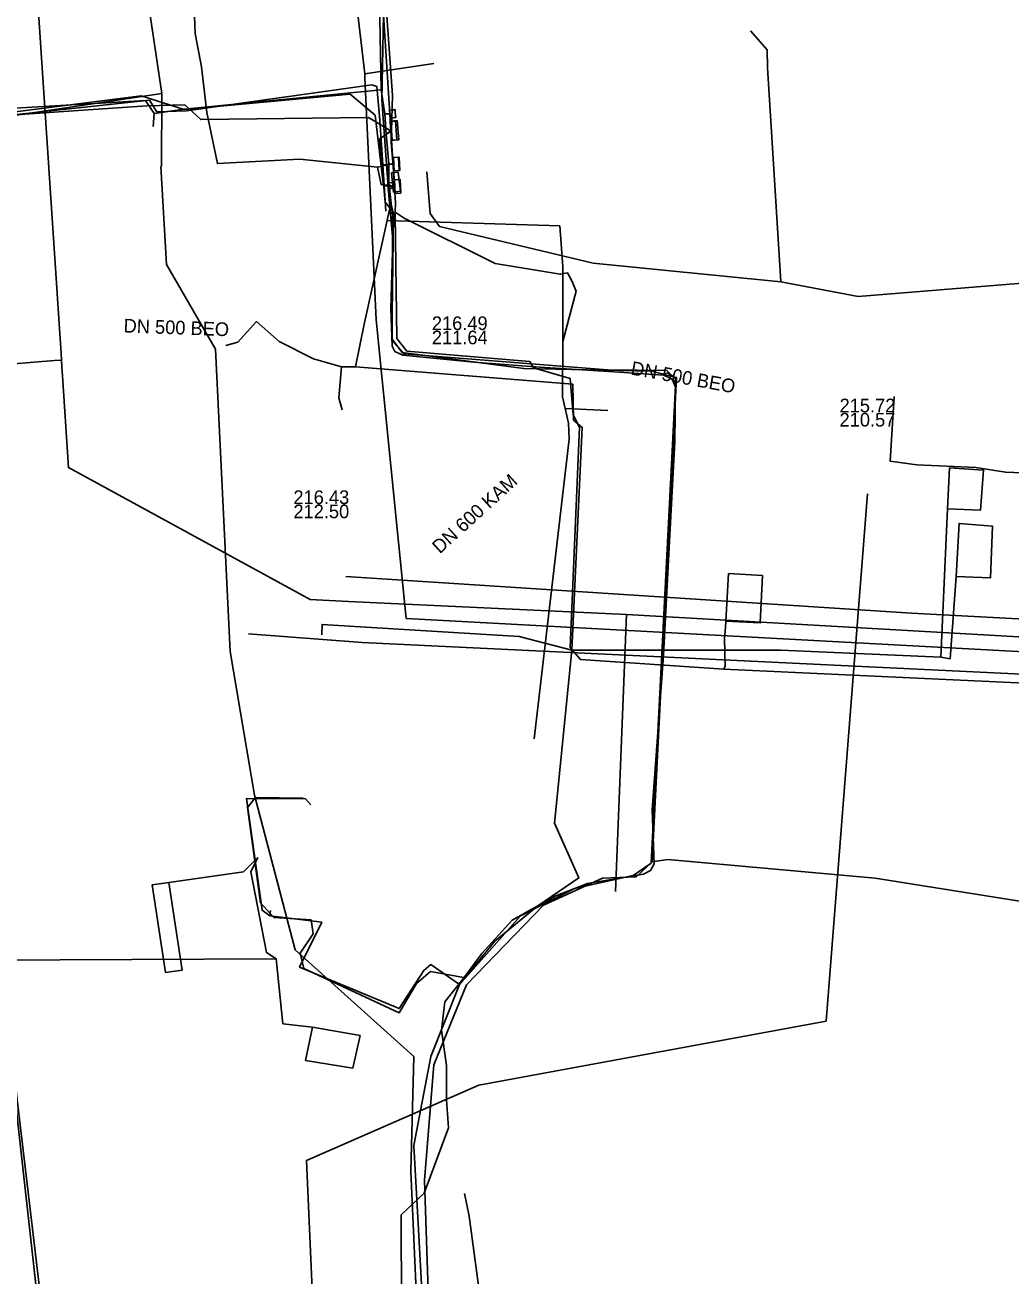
# Model space of a CAD drawing. Extents: x -599951 to -598963, y -1164095 to -1162939.
# Drawn here: x -599224.6 to -599166.8, y -1163195.6 to -1163122.3 of the extents above; entities that cross this region are included whole.
import ezdxf

# ---------------------------------------------------------------- set-up
doc = ezdxf.new("R2010")
doc.units = 0
for name, color, linetype in [('Vrstva 1', 7, 'Continuous'), ('Vrstva 12', 7, 'Continuous'), ('Vrstva 13', 7, 'Continuous'), ('Vrstva 15', 7, 'Continuous'), ('Vrstva 19', 7, 'Continuous'), ('Vrstva 32', 7, 'Continuous'), ('Vrstva 33', 7, 'Continuous'), ('Vrstva 42', 7, 'Continuous'), ('Vrstva 55', 7, 'Continuous')]:
    doc.layers.add(name, color=color, linetype=linetype)

msp = doc.modelspace()

# ---------------------------------------------------------------- linework, layer by layer
at = {"layer": 'Vrstva 1'}
for p, q in [((-599177.61, -1163180.7), (-599175.2, -1163149.78)), ((-599205.781, -1163154.619), (-599172.62, -1163156.78)), ((-599197.98, -1163184.46), (-599177.61, -1163180.7)), ((-599208.09, -1163188.88), (-599197.98, -1163184.46)), ((-599205.93, -1163237.75), (-599208.09, -1163188.88))]:
    msp.add_line(p, q, dxfattribs=at)
msp.add_lwpolyline([(-599172.62, -1163156.78), (-599149.802, -1163157.987), (-599149.672, -1163157.994), (-599123.67, -1163159.37)], dxfattribs=at)
at = {"layer": 'Vrstva 12'}
for points in [[(-599203.9, -1163116.45), (-599202.86, -1163132.72)], [(-599202.86, -1163132.72), (-599202.88, -1163133.26)], [(-599203.4, -1163133.74), (-599193.24, -1163134.06)], [(-599202.88, -1163133.26), (-599202.35, -1163133.61), (-599197.03, -1163136.27), (-599193.21, -1163136.9), (-599192.78, -1163136.82), (-599192.52, -1163137.29)], [(-599193.24, -1163134.06), (-599193.06, -1163136.45), (-599193.06, -1163140.85)], [(-599192.52, -1163137.29), (-599192.27, -1163137.9)], [(-599192.27, -1163137.9), (-599193.06, -1163140.85)], [(-599193.06, -1163140.85), (-599193.07, -1163144.08), (-599192.92, -1163144.77), (-599192.72, -1163145.64), (-599192.68, -1163146.57), (-599194.74, -1163164.15)], [(-599192.92, -1163144.77), (-599190.42, -1163144.89)]]:
    msp.add_lwpolyline(points, dxfattribs=at)
at = {"layer": 'Vrstva 13'}
for p, q in [((-599222.459, -1163141.943), (-599222.86, -1163141.962)), ((-599222.48, -1163141.54), (-599222.459, -1163141.943)), ((-599222.459, -1163141.943), (-599222.436, -1163142.346)), ((-599189.333, -1163156.861), (-599189.975, -1163173.104))]:
    msp.add_line(p, q, dxfattribs=at)
for points in [[(-599222.48, -1163141.54), (-599225.813, -1163091.244), (-599226.95, -1163073.028), (-599227.2, -1163068.43), (-599228.87, -1163033.039), (-599230.239, -1163003.571), (-599231.6, -1162981.64), (-599231.989, -1162975.173), (-599237.493, -1162958.648), (-599238.774, -1162939.4)], [(-599280.123, -1163149.708), (-599279.79, -1163149.777), (-599275.388, -1163146.114), (-599242.43, -1163143.42), (-599230.497, -1163142.575), (-599222.86, -1163141.962)], [(-599130.31, -1163160.22), (-599189.333, -1163156.861), (-599205.614, -1163156.096), (-599207.862, -1163155.979), (-599222.044, -1163148.234), (-599222.388, -1163142.862), (-599222.435, -1163142.347)]]:
    msp.add_lwpolyline(points, dxfattribs=at)
at = {"layer": 'Vrstva 15'}
for points in [[(-599180.27, -1163137.35), (-599181.06, -1163124.77), (-599181.08, -1163123.74), (-599182.06, -1163122.62)], [(-599201.03, -1163130.89), (-599200.83, -1163133.34), (-599200.28, -1163134.1), (-599191.27, -1163136.25), (-599180.27, -1163137.35), (-599175.74, -1163138.21), (-599163.96, -1163137.25), (-599162.62, -1163136.68), (-599160.77, -1163135.04), (-599159.09, -1163134.93), (-599156.43, -1163135.23), (-599143.01, -1163137.71), (-599139.31, -1163138.65), (-599134.15, -1163140.36), (-599131.8, -1163141.93), (-599124.57, -1163147.85), (-599121.93, -1163149.57), (-599112.04, -1163149.89), (-599105.46, -1163150.46), (-599101.38, -1163150.63), (-599100.41, -1163147.13)]]:
    msp.add_lwpolyline(points, dxfattribs=at)
at = {"layer": 'Vrstva 19'}
for points in [[(-599206.6, -1163097.62), (-599206.66, -1163104.38), (-599206.18, -1163112.36), (-599204.67, -1163125.142), (-599204.659, -1163125.373), (-599204, -1163139.58), (-599202.25, -1163157.09)], [(-599200.617, -1163124.537), (-599204.67, -1163125.142)], [(-599126.72, -1163161.13), (-599152.24, -1163159.78), (-599202.25, -1163157.09)]]:
    msp.add_lwpolyline(points, dxfattribs=at)
at = {"layer": 'Vrstva 32'}
for points in [[(-599222.613, -1163059.102), (-599221.79, -1163069.961), (-599221.63, -1163076.503), (-599220.767, -1163090.512), (-599220.116, -1163099.129), (-599218.776, -1163101.181), (-599218.358, -1163101.811), (-599217.879, -1163103.868), (-599215.997, -1163114.831), (-599215.375, -1163115.418), (-599214.491, -1163115.536), (-599212.188, -1163114.604), (-599210.126, -1163113.927), (-599206.06, -1163113.183), (-599203.799, -1163115.697), (-599203.049, -1163126.417), (-599203.124, -1163129.182), (-599202.924, -1163131.478)], [(-599161.8, -1163148.72), (-599167.11, -1163148.5), (-599168.85, -1163148.23), (-599172.31, -1163148.08), (-599173.86, -1163147.87), (-599173.639, -1163144.069)]]:
    msp.add_lwpolyline(points, dxfattribs=at)
at = {"layer": 'Vrstva 33'}
for points in [[(-599203.22, -1163127.27), (-599203.17, -1163127.74), (-599202.852, -1163127.706), (-599202.902, -1163127.236)], [(-599202.89, -1163127.256), (-599202.87, -1163127.716), (-599203.19, -1163127.73), (-599203.21, -1163127.27)], [(-599203.19, -1163127.95), (-599203.1, -1163129.05), (-599202.781, -1163129.024), (-599202.871, -1163127.924)], [(-599202.772, -1163127.89), (-599202.682, -1163129.01), (-599203.06, -1163129.04), (-599203.15, -1163127.92)], [(-599203.01, -1163130.05), (-599202.97, -1163130.84), (-599202.65, -1163130.824), (-599202.69, -1163130.034)], [(-599202.661, -1163130.034), (-599202.621, -1163130.814), (-599202.94, -1163130.83), (-599202.98, -1163130.05)], [(-599202.702, -1163130.917), (-599202.582, -1163132.037), (-599202.98, -1163132.08), (-599203.1, -1163130.96)], [(-599202.92, -1163131.36), (-599202.88, -1163132.16), (-599202.56, -1163132.144), (-599202.6, -1163131.344)]]:
    msp.add_lwpolyline(points, close=True, dxfattribs=at)
at = {"layer": 'Vrstva 42'}
for p, q in [((-599244.136, -1163129.788), (-599217.775, -1163126.435)), ((-599244.136, -1163129.788), (-599217.775, -1163126.435)), ((-599217.775, -1163126.435), (-599215.263, -1163127.234)), ((-599217.775, -1163126.435), (-599215.263, -1163127.234)), ((-599215.263, -1163127.234), (-599205.518, -1163126.343)), ((-599215.263, -1163127.234), (-599205.518, -1163126.343)), ((-599205.518, -1163126.343), (-599204.051, -1163127.581)), ((-599205.518, -1163126.343), (-599204.051, -1163127.581)), ((-599217.02, -1163127.48), (-599217.07, -1163128.24)), ((-599204.051, -1163127.581), (-599203.569, -1163131.721)), ((-599204.051, -1163127.581), (-599203.569, -1163131.721)), ((-599203.49, -1163127.49), (-599203.2, -1163127.5)), ((-599203.41, -1163128.69), (-599203.105, -1163128.48)), ((-599202.99, -1163130.448), (-599203.618, -1163130.489)), ((-599202.99, -1163130.448), (-599203.618, -1163130.489)), ((-599203.26, -1163130.42), (-599202.96, -1163130.44)), ((-599203.569, -1163131.721), (-599202.9, -1163131.76)), ((-599203.569, -1163131.721), (-599202.9, -1163131.76)), ((-599203.25, -1163131.53), (-599203.04, -1163131.52)), ((-599210.24, -1163174.52), (-599210.2, -1163174.22))]:
    msp.add_line(p, q, dxfattribs=at)
for points in [[(-599202.95, -1163131.708), (-599203.71, -1163131.63), (-599203.92, -1163130.62), (-599208.48, -1163130.16), (-599213.31, -1163130.41), (-599213.93, -1163127.42), (-599214.25, -1163124.73), (-599214.61, -1163122.78), (-599214.71, -1163120.22), (-599214.44, -1163119.01), (-599213.88, -1163117.44), (-599215.41, -1163115.25), (-599218.37, -1163101.62), (-599219.91, -1163098.93), (-599220.38, -1163097.91), (-599221.18, -1163095.56), (-599221.74, -1163087.69), (-599222.75, -1163070.74), (-599223.51, -1163055.7)], [(-599202.995, -1163130.415), (-599203.92, -1163130.62), (-599208.48, -1163130.16), (-599213.31, -1163130.41), (-599213.93, -1163127.42), (-599214.25, -1163124.73), (-599214.61, -1163122.78), (-599214.71, -1163120.22), (-599214.44, -1163119.01), (-599213.88, -1163117.44), (-599215.41, -1163115.25), (-599218.37, -1163101.62), (-599219.91, -1163098.93), (-599220.38, -1163097.91), (-599221.18, -1163095.56), (-599221.74, -1163087.69), (-599222.75, -1163070.74), (-599223.51, -1163055.7)], [(-599215.26, -1163127.21), (-599203.7, -1163126.08), (-599203.94, -1163113.52), (-599204.31, -1163113.25), (-599204.36, -1163112.54), (-599204.84, -1163102.6)], [(-599199.76, -1163186.96), (-599199.88, -1163185.32), (-599199.88, -1163183.31), (-599200.18, -1163181.22), (-599199.98, -1163179.56), (-599198.92, -1163178.24), (-599197.81, -1163176.73), (-599196.02, -1163174.78), (-599193.46, -1163173.35), (-599191.61, -1163172.62), (-599188.32, -1163172.08), (-599187.91, -1163171.87), (-599187.71, -1163171.48), (-599187.82, -1163168.31), (-599187.15, -1163159.23), (-599186.81, -1163152.56), (-599186.49, -1163146.71), (-599186.45, -1163143.53), (-599186.65, -1163143.05), (-599187.14, -1163142.82), (-599190.36, -1163142.61), (-599194.42, -1163142.34), (-599198.28, -1163142.05), (-599202.43, -1163141.64), (-599202.9, -1163141.43), (-599203.07, -1163141.12), (-599203.15, -1163138.93), (-599203.03, -1163134.9), (-599203.27, -1163132.04), (-599203.67, -1163126.68), (-599203.57, -1163121.67)], [(-599203.44, -1163133.2), (-599203.618, -1163130.489), (-599203.79, -1163127.87), (-599203.97, -1163125.9), (-599204.26, -1163125.79), (-599215.12, -1163127.32), (-599216.86, -1163127.37), (-599217.29, -1163126.7), (-599244.45, -1163129.63), (-599245.88, -1163130.11), (-599247.87, -1163130.56), (-599248.24, -1163131.21), (-599248.16, -1163134.29), (-599248.03, -1163135.56), (-599248.57, -1163137.95), (-599249.12, -1163139.05), (-599251.4, -1163141), (-599252.28, -1163141.17), (-599256.52, -1163141.46), (-599262.16, -1163142.19), (-599265.02, -1163142.81), (-599265.67, -1163142.86), (-599267.06, -1163143.01), (-599270.814, -1163143.415)], [(-599203.16, -1163132.85), (-599203.25, -1163131.53), (-599203.26, -1163130.42), (-599203.41, -1163128.69), (-599203.49, -1163127.49), (-599203.7, -1163126.08)], [(-599244.436, -1163129.83), (-599233.795, -1163128.148), (-599217.451, -1163127.025)], [(-599233.82, -1163127.66), (-599217.52, -1163126.72), (-599217.02, -1163127.48), (-599215.26, -1163127.21)], [(-599217.451, -1163127.025), (-599215.227, -1163126.974), (-599214.285, -1163127.833), (-599204.448, -1163127.705), (-599203.124, -1163128.516)], [(-599203.124, -1163128.516), (-599203.8, -1163128.964), (-599203.468, -1163132.668), (-599202.881, -1163133.389), (-599202.788, -1163140.676), (-599202.2, -1163141.408), (-599194.983, -1163142.026), (-599194.78, -1163142.398), (-599192.62, -1163143.02), (-599192.459, -1163145.143), (-599192.087, -1163145.87)], [(-599202.99, -1163130.445), (-599203.37, -1163130.47), (-599203.04, -1163133.45), (-599203.06, -1163140.76), (-599202.37, -1163141.56), (-599190.43, -1163142.51), (-599186.95, -1163142.54), (-599186.43, -1163143.06), (-599187.88, -1163171.44), (-599188.93, -1163172.16), (-599192.37, -1163172.93), (-599195.54, -1163174.52), (-599198.76, -1163178.17), (-599200.82, -1163177.79), (-599201.64, -1163178.5), (-599202.66, -1163180.21), (-599208.24, -1163177.62), (-599208.46, -1163176.72), (-599207.7, -1163175.59), (-599207.82, -1163174.76), (-599210, -1163174.63), (-599210.78, -1163173.76), (-599211.55, -1163168.18), (-599211.07, -1163167.58), (-599208.29, -1163167.63)], [(-599202.99, -1163130.445), (-599203.37, -1163130.47), (-599203.04, -1163133.45), (-599203.06, -1163140.76), (-599202.37, -1163141.56), (-599190.43, -1163142.51), (-599186.95, -1163142.54), (-599186.43, -1163143.06), (-599187.88, -1163171.44), (-599188.93, -1163172.16), (-599192.37, -1163172.93), (-599195.54, -1163174.52), (-599198.76, -1163178.17), (-599200.82, -1163177.79), (-599201.64, -1163178.5), (-599202.66, -1163180.21), (-599208.24, -1163177.62), (-599208.46, -1163176.72), (-599207.7, -1163175.59), (-599207.82, -1163174.76), (-599210, -1163174.63), (-599210.78, -1163173.76), (-599211.55, -1163168.18), (-599211.07, -1163167.58), (-599208.29, -1163167.63)], [(-599200.874, -1163198.84), (-599201.163, -1163190.018), (-599200.617, -1163183.263), (-599198.712, -1163178.575), (-599194.181, -1163173.908), (-599190.737, -1163172.31), (-599188.762, -1163172.23), (-599187.811, -1163171.359), (-599186.388, -1163142.956), (-599187.852, -1163142.582), (-599195.346, -1163142.426), (-599202.486, -1163141.494), (-599203.088, -1163140.697), (-599202.978, -1163133.439), (-599203.29, -1163131.948), (-599202.9, -1163131.76)], [(-599187.811, -1163171.359), (-599186.388, -1163142.956), (-599187.852, -1163142.582), (-599195.346, -1163142.426), (-599202.486, -1163141.494), (-599203.088, -1163140.697), (-599202.978, -1163133.439), (-599203.29, -1163131.948), (-599202.9, -1163131.76)], [(-599200.874, -1163198.84), (-599201.163, -1163190.018), (-599200.617, -1163183.263), (-599198.712, -1163178.575), (-599194.181, -1163173.908), (-599190.737, -1163172.31), (-599188.762, -1163172.23), (-599187.811, -1163171.359), (-599186.388, -1163142.956), (-599187.852, -1163142.582), (-599195.346, -1163142.426), (-599202.486, -1163141.494), (-599203.088, -1163140.697), (-599202.978, -1163133.439), (-599203.29, -1163131.948), (-599202.9, -1163131.76)], [(-599203.16, -1163132.85), (-599204.7, -1163139.83), (-599205.22, -1163142.33), (-599206.03, -1163142.33), (-599207.68, -1163141.86), (-599209.68, -1163140.85), (-599211.01, -1163139.68), (-599212.12, -1163140.89), (-599212.81, -1163141.08)], [(-599206.03, -1163142.33), (-599206.19, -1163144.14), (-599206, -1163144.85)], [(-599205.22, -1163142.33), (-599192.48, -1163143.34), (-599192.44, -1163145.45), (-599191.92, -1163145.88), (-599192.52, -1163158.94), (-599193.54, -1163169.1)], [(-599192.087, -1163145.87), (-599192.62, -1163158.795)], [(-599170.89, -1163159.36), (-599170.51, -1163150.66), (-599170.38, -1163148.26), (-599168.39, -1163148.38), (-599168.56, -1163150.73), (-599170.51, -1163150.66)], [(-599170.34, -1163159.46), (-599170, -1163154.62), (-599169.82, -1163151.51), (-599167.86, -1163151.68), (-599167.98, -1163154.7), (-599170, -1163154.62)], [(-599183.531, -1163159.88), (-599183.575, -1163158.258), (-599183.527, -1163157.619), (-599183.504, -1163157.253), (-599183.335, -1163154.452), (-599181.352, -1163154.57), (-599181.478, -1163157.343), (-599183.504, -1163157.253)], [(-599192.52, -1163158.94), (-599195.61, -1163158.14), (-599207.17, -1163157.44), (-599207.18, -1163158.04)], [(-599192.62, -1163158.795), (-599192.014, -1163159.485), (-599183.615, -1163160.063), (-599164.285, -1163160.958), (-599144.058, -1163162.227), (-599122.997, -1163163.203), (-599102.445, -1163164.313), (-599100.049, -1163163.5), (-599097.021, -1163164.314), (-599079.053, -1163165.477), (-599054.213, -1163166.656)], [(-599192.52, -1163158.94), (-599180.28, -1163158.94), (-599170.89, -1163159.36), (-599170.34, -1163159.46)], [(-599183.615, -1163160.063), (-599183.531, -1163159.88)], [(-599199.12, -1163178.56), (-599200.79, -1163177.38), (-599201.21, -1163177.73), (-599202.65, -1163179.96), (-599208.49, -1163177.53), (-599207.19, -1163174.9), (-599210.24, -1163174.52), (-599210.69, -1163174.2), (-599211.61, -1163167.65), (-599208.14, -1163167.67), (-599207.83, -1163168.01)], [(-599193.54, -1163169.1), (-599192.12, -1163172.3), (-599194.52, -1163173.94), (-599197.04, -1163176.01), (-599199.12, -1163178.56)], [(-599210.93, -1163171.1), (-599211.784, -1163171.946), (-599216.15, -1163172.577), (-599217.143, -1163172.714), (-599216.361, -1163177.841), (-599215.368, -1163177.704), (-599216.15, -1163172.577)], [(-599209.865, -1163177.042), (-599210.424, -1163176.681), (-599211.358, -1163171.942), (-599210.93, -1163171.1)], [(-599187.811, -1163171.359), (-599186.91, -1163171.23), (-599174.75, -1163172.32), (-599160.38, -1163174.6)], [(-599187.811, -1163171.359), (-599186.91, -1163171.23), (-599174.75, -1163172.32), (-599160.38, -1163174.6)], [(-599209.47, -1163180.85), (-599209.865, -1163177.042), (-599226.778, -1163177.129), (-599234.397, -1163177.361)], [(-599221.184, -1163240.787), (-599222.1, -1163221.513), (-599222.943, -1163208.768), (-599223.097, -1163207.287), (-599223.22, -1163204.278), (-599223.353, -1163199.634), (-599225.94, -1163177.72), (-599226.778, -1163177.129)], [(-599199.12, -1163178.56), (-599200.8, -1163182.77), (-599201.8, -1163188), (-599201.17, -1163199.29), (-599200.43, -1163213.65), (-599199.84, -1163224.77), (-599198.81, -1163240.75), (-599198.05, -1163254.67)], [(-599209.47, -1163180.85), (-599207.739, -1163181.056), (-599208.142, -1163183.012), (-599205.378, -1163183.449), (-599204.946, -1163181.547), (-599207.739, -1163181.056)], [(-599199.76, -1163186.96), (-599201.189, -1163190.798), (-599202.535, -1163192.056), (-599202.497, -1163202.89)], [(-599190.216, -1163256.134), (-599192.57, -1163256.19), (-599193.23, -1163255.97), (-599193.53, -1163255.34), (-599194.08, -1163251.1), (-599194.01, -1163247.4), (-599193.49, -1163237.69), (-599193.68, -1163230.54), (-599194.61, -1163216.72), (-599195.64, -1163210.19), (-599197.26, -1163201.74), (-599198.55, -1163192.13), (-599198.825, -1163190.799)]]:
    msp.add_lwpolyline(points, dxfattribs=at)
at = {"layer": 'Vrstva 55'}
for points in [[(-599216.56, -1163126.31), (-599217.56, -1163119.6), (-599214.96, -1163114.19), (-599218.381, -1163101.424)], [(-599216.56, -1163126.31), (-599248, -1163131), (-599246.84, -1163137.44)], [(-599216.56, -1163126.31), (-599216.594, -1163130.578)], [(-599216.618, -1163130.58), (-599216.302, -1163136.335), (-599213.415, -1163141.3), (-599212.56, -1163159.02), (-599211.136, -1163167.452), (-599208.743, -1163176.511), (-599201.792, -1163182.778), (-599201.963, -1163189.502), (-599201.087, -1163209.241)], [(-599150.28, -1163161.112), (-599204.82, -1163158.49), (-599211.49, -1163157.98)], [(-599216.968, -1163302.477), (-599218.15, -1163286.65), (-599221.43, -1163231.79), (-599222.71, -1163207.36), (-599225.57, -1163181.59), (-599225.876, -1163178.192)]]:
    msp.add_lwpolyline(points, dxfattribs=at)

# ---------------------------------------------------------------- texts
at = {"layer": 'Vrstva 12'}
for s, rotation, p in [('DN 500 BEO', 357.88818, (-599218.821, -1163140.309)), ('DN 500 BEO', 349.68229, (-599189.11, -1163142.777)), ('DN 600 KAM', 42.22273, (-599200.271, -1163153.33))]:
    msp.add_text(s, height=0.8, rotation=rotation, dxfattribs=at).set_placement(p)
for s, p in [('216.49', (-599200.736, -1163140.173)), ('211.64', (-599200.736, -1163141.005)), ('215.72', (-599176.833, -1163144.998)), ('210.57', (-599176.833, -1163145.83)), ('216.43', (-599208.853, -1163150.376)), ('212.50', (-599208.853, -1163151.208))]:
    msp.add_text(s, height=0.8, dxfattribs=at).set_placement(p)

doc.saveas('drawing.dxf')
